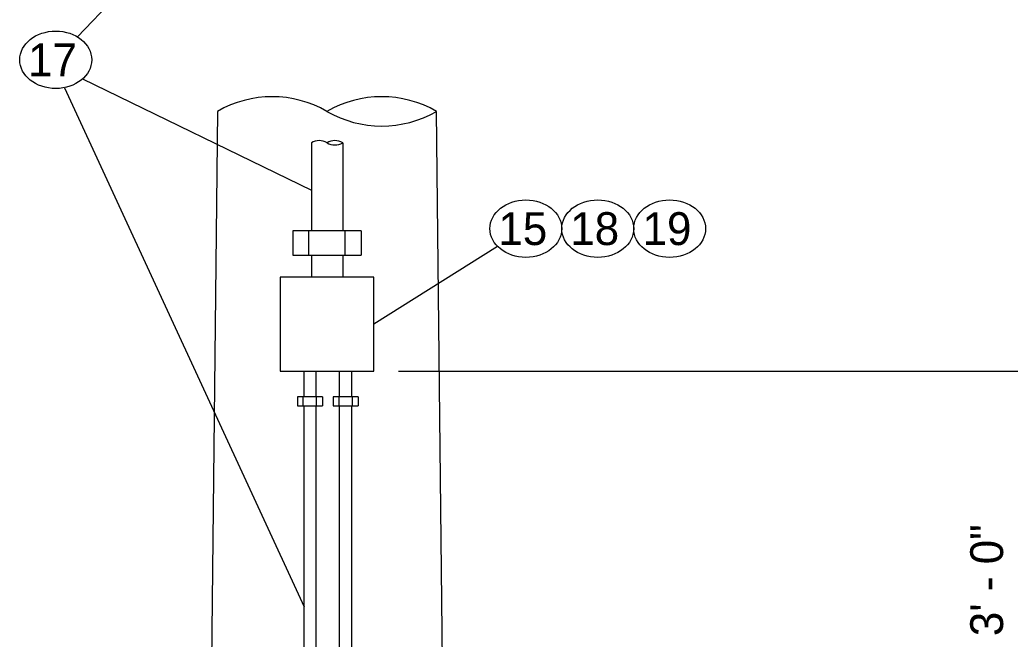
# Model space of a CAD drawing. Extents: x 99862 to 104211, y 98939 to 102076.
# Drawn here: x 100830.1 to 101312.4, y 101084 to 101385.5 of the extents above; entities that cross this region are included whole.
import ezdxf

# ---------------------------------------------------------------- set-up
doc = ezdxf.new("R2010")
doc.units = 0
for name, color, linetype in [('Level 1', 7, 'Continuous'), ('Level 15', 7, 'Continuous'), ('Level 20', 7, 'Continuous'), ('Level 24', 7, 'Continuous'), ('Level 7', 7, 'Continuous'), ('Level 8', 7, 'Continuous')]:
    doc.layers.add(name, color=color, linetype=linetype)

msp = doc.modelspace()

# ---------------------------------------------------------------- linework, layer by layer
at = {"layer": 'Level 1'}
for p, q in [((100926.3, 101340.94), (100921.22, 100872.66)), ((101038.18, 100865.38), (101033.01, 101340.94))]:
    msp.add_line(p, q, dxfattribs=at)
for centre, start, end in [((100952.98, 101294.74), 60, 120), ((101006.33, 101294.74), 60, 120), ((101006.33, 101387.15), 240, 300)]:
    msp.add_arc(centre, 53.35, start, end, dxfattribs=at)
at = {"layer": 'Level 15'}
for p, q in [((100858.19, 101377.17), (100926.57, 101448.87)), ((100860.68, 101356.76), (100972.06, 101302.62)), ((100851.87, 101352.47), (100968.49, 101099.81)), ((101062.75, 101275.21), (101002.48, 101237.33)), ((101014.48, 101214.51), (101332.92, 101214.51))]:
    msp.add_line(p, q, dxfattribs=at)
at = {"layer": 'Level 20'}
for centre in [(100847.57, 101366.04), (101076.52, 101283.85), (101111.52, 101283.85), (101146.52, 101283.85)]:
    msp.add_ellipse(centre, major_axis=(-17.5, 0), ratio=0.8, dxfattribs=at)
at = {"layer": 'Level 24'}
for p, q in [((100972.06, 101325.66), (100972.06, 101282.75)), ((100987.34, 101325.66), (100987.34, 101282.75)), ((100972.06, 101270.98), (100972.06, 101260.16)), ((100987.34, 101270.98), (100987.34, 101260.16))]:
    msp.add_line(p, q, dxfattribs=at)
for centre, start, end in [((100975.88, 101319.04), 60, 120), ((100983.52, 101319.04), 60, 120), ((100983.52, 101332.27), 240, 300)]:
    msp.add_arc(centre, 7.64, start, end, dxfattribs=at)
at = {"layer": 'Level 7'}
for p, q in [((100985.84, 101201.94), (100985.84, 101214.51)), ((100991.76, 101201.94), (100991.76, 101214.51)), ((100985.84, 100915.09), (100985.84, 101197.66)), ((100991.76, 100915.25), (100991.76, 101197.66))]:
    msp.add_line(p, q, dxfattribs=at)
at = {"layer": 'Level 8'}
for p, q in [((100963.05, 101282.75), (100963.05, 101270.98)), ((100996.39, 101282.75), (100963.05, 101282.75)), ((100970.89, 101270.92), (100970.89, 101282.69)), ((100988.55, 101270.92), (100988.55, 101282.69)), ((100996.39, 101282.75), (100996.39, 101270.98)), ((100963.05, 101270.98), (100996.39, 101270.98)), ((100968.49, 101201.94), (100968.49, 101214.51)), ((100974.19, 101214.51), (100974.19, 101201.94)), ((100965.28, 101201.94), (100965.28, 101197.66)), ((100977.41, 101201.94), (100965.28, 101201.94)), ((100968.14, 101197.64), (100968.14, 101201.92)), ((100974.56, 101197.64), (100974.56, 101201.92)), ((100977.41, 101201.94), (100977.41, 101197.66)), ((100982.75, 101201.94), (100982.75, 101197.66)), ((100994.88, 101201.94), (100982.75, 101201.94)), ((100985.6, 101197.64), (100985.6, 101201.92)), ((100992.02, 101197.64), (100992.02, 101201.92)), ((100994.88, 101201.94), (100994.88, 101197.66)), ((100965.28, 101197.66), (100977.41, 101197.66)), ((100968.49, 100922.59), (100968.49, 101197.66)), ((100974.19, 101197.66), (100974.19, 100922.59)), ((100982.75, 101197.66), (100994.88, 101197.66))]:
    msp.add_line(p, q, dxfattribs=at)
msp.add_lwpolyline([(101002.48, 101260.16), (100956.83, 101260.16), (100956.83, 101214.51), (101002.48, 101214.51)], close=True, dxfattribs=at)

# ---------------------------------------------------------------- texts
at = {"layer": 'Level 20'}
for s, p in [('17', (100834.12, 101358.04)), ('15', (101063.14, 101275.86)), ('18', (101098.14, 101275.86)), ('19', (101133.35, 101275.86))]:
    msp.add_text(s, height=16, dxfattribs=at).set_placement(p)
msp.add_text('3\' - 0"', height=16, rotation=90, dxfattribs=at).set_placement((101308.92, 101085.46))

doc.saveas('drawing.dxf')
